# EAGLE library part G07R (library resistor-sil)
SIL RESISTOR
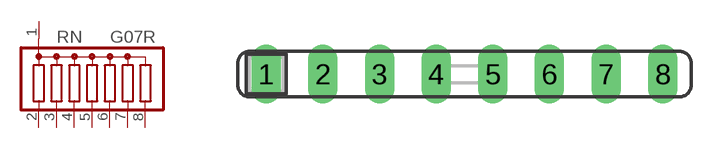
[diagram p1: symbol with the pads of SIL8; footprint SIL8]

Designator prefix RN

## G07R (OC_FARNELL: unknown; OC_NEWARK: unknown)  [SIL8]
1  1  pas
2  2  pas
3  3  pas
4  4  pas
5  5  pas
6  6  pas
7  7  pas
8  8  pas

## Footprint SIL8 (pad centres in mm)
Single In Line
drill 0.813 long: 1 -8.89,0; 2 -6.35,0; 3 -3.81,0; 4 -1.27,0; 5 1.27,0; 6 3.81,0; 7 6.35,0; 8 8.89,0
